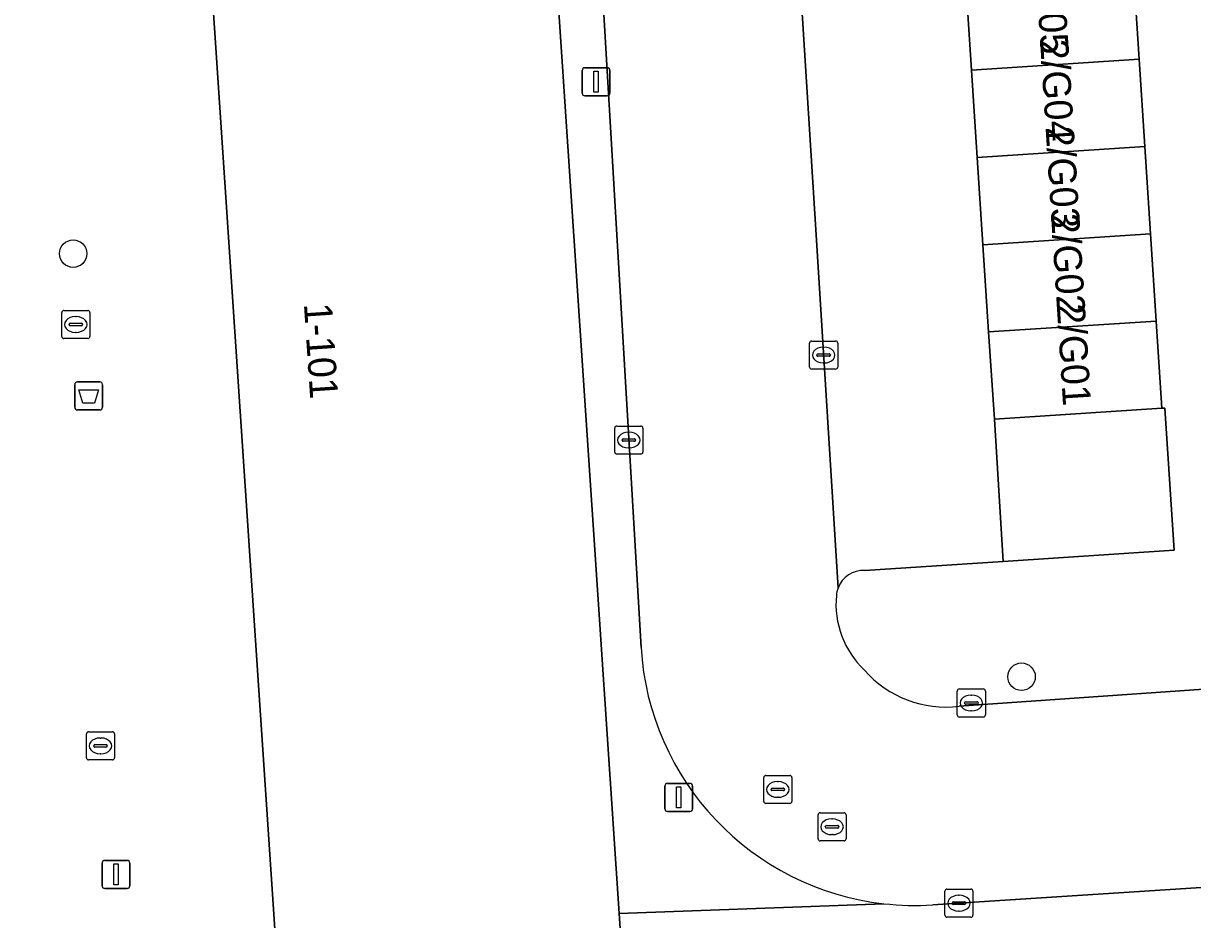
# Model space of a CAD drawing. Extents: x 159680 to 160786, y 387323 to 388340.
# Drawn here: x 160312.93 to 160354.58, y 387760.4 to 387792.33 of the extents above; entities that cross this region are included whole.
import ezdxf

# ---------------------------------------------------------------- set-up
doc = ezdxf.new("R2010")
doc.units = 0
for name, color, linetype in [('IMGEO_Afvalbak', 7, 'Continuous'), ('IMGEO_Boom', 7, 'Continuous'), ('IMGEO_Brandkraan', 7, 'Continuous'), ('IMGEO_Groenvoorziening', 7, 'Continuous'), ('IMGEO_Kolk', 7, 'Continuous'), ('IMGEO_Lichtmast', 7, 'Continuous'), ('IMGEO_Pand', 7, 'Continuous'), ('IMGEO_Pand_nummerreeks', 7, 'Continuous'), ('IMGEO_Parkeervlak_open', 7, 'Continuous'), ('IMGEO_Rijbaan_lokaal_open', 7, 'Continuous'), ('IMGEO_Rioolput', 7, 'Continuous'), ('IMGEO_Voetpad_open', 7, 'Continuous')]:
    doc.layers.add(name, color=color, linetype=linetype)

msp = doc.modelspace()

# ---------------------------------------------------------------- linework, layer by layer
at = {"layer": 'IMGEO_Afvalbak'}
for p, q in [((160314.86, 387779.559), (160315.65, 387779.559)), ((160315.65, 387779.559), (160314.86, 387779.559)), ((160314.76, 387778.659), (160314.76, 387779.459)), ((160314.76, 387779.459), (160314.76, 387778.659)), ((160315.75, 387779.459), (160315.75, 387778.659)), ((160315.75, 387778.659), (160315.75, 387779.459)), ((160315.65, 387778.559), (160314.86, 387778.559)), ((160314.86, 387778.559), (160315.65, 387778.559))]:
    msp.add_line(p, q, dxfattribs=at)
msp.add_lwpolyline([(160314.903, 387779.273), (160315.607, 387779.273), (160315.458, 387778.803), (160315.052, 387778.803), (160314.903, 387779.273)], dxfattribs=at)
for centre, start, end in [((160314.86, 387779.459), 90, 180), ((160314.86, 387779.459), 90, 180), ((160315.65, 387779.459), 0, 90), ((160315.65, 387779.459), 360, 90), ((160314.86, 387778.659), 180, 270), ((160314.86, 387778.659), 180, 270), ((160315.65, 387778.659), 270, 0), ((160315.65, 387778.659), 270, 0)]:
    msp.add_arc(centre, 0.1, start, end, dxfattribs=at)
at = {"layer": 'IMGEO_Boom'}
for centre in [(160314.705, 387784.129), (160348.491, 387769.055)]:
    msp.add_circle(centre, 0.489, dxfattribs=at)
at = {"layer": 'IMGEO_Brandkraan'}
for p, q in [((160341.315, 387764.207), (160342.167, 387764.207)), ((160341.24, 387763.281), (160341.24, 387764.133)), ((160341.542, 387763.75), (160341.94, 387763.75)), ((160341.728, 387763.987), (160341.753, 387763.987)), ((160342.241, 387764.133), (160342.241, 387763.281)), ((160341.499, 387763.701), (160341.499, 387763.713)), ((160341.937, 387763.664), (160341.539, 387763.664)), ((160341.751, 387763.427), (160341.726, 387763.427)), ((160341.983, 387763.713), (160341.983, 387763.701)), ((160342.167, 387763.207), (160341.315, 387763.207))]:
    msp.add_line(p, q, dxfattribs=at)
for points in [[(160341.315, 387764.207), (160342.167, 387764.207)], [(160341.24, 387763.281), (160341.24, 387764.133)], [(160342.241, 387764.133), (160342.241, 387763.281)], [(160342.167, 387763.207), (160341.315, 387763.207)]]:
    msp.add_lwpolyline(points, dxfattribs=at)
for centre, radius, start, end in [((160341.317, 387764.131), 0.0765, 91.552, 178.448), ((160341.317, 387764.131), 0.0765, 91.552, 178.448), ((160342.165, 387764.131), 0.0765, 1.552, 88.448), ((160342.165, 387764.131), 0.0765, 1.552, 88.448), ((160341.539, 387763.71), 0.0403, 85.8775, 175.7526), ((160341.944, 387763.712), 0.0386, 1.7309, 96.639), ((160341.536, 387763.7), 0.0366, 178.938, 274.7102), ((160341.94, 387763.707), 0.043, 264.8664, 352.4533), ((160341.317, 387763.283), 0.0765, 181.552, 268.448), ((160341.317, 387763.283), 0.0765, 181.552, 268.448), ((160342.165, 387763.283), 0.0765, 271.552, 358.448), ((160342.165, 387763.283), 0.0765, 271.552, 358.448)]:
    msp.add_arc(centre, radius, start, end, dxfattribs=at)
for centre, major_axis, ratio, start_param, end_param in [((160341.727, 387763.707), (-0.387, 0.002), 0.722429, 4.712389, 7.853982), ((160341.752, 387763.707), (-0.39, 0.002), 0.717154, 1.570796, 4.712389)]:
    msp.add_ellipse(centre, major_axis=major_axis, ratio=ratio, start_param=start_param, end_param=end_param, dxfattribs=at)
at = {"layer": 'IMGEO_Groenvoorziening'}
msp.add_lwpolyline([(160347.83, 387773.164), (160353.929, 387773.561), (160353.599, 387778.626), (160353.494, 387778.619), (160347.522, 387778.23)], close=True, dxfattribs=at)
at = {"layer": 'IMGEO_Kolk'}
for p, q in [((160314.373, 387782.105), (160315.225, 387782.105)), ((160314.298, 387781.179), (160314.298, 387782.031)), ((160314.6, 387781.648), (160314.998, 387781.648)), ((160314.786, 387781.885), (160314.811, 387781.885)), ((160315.299, 387782.031), (160315.299, 387781.179)), ((160314.557, 387781.599), (160314.557, 387781.611)), ((160314.995, 387781.562), (160314.597, 387781.562)), ((160314.809, 387781.325), (160314.784, 387781.325)), ((160315.041, 387781.611), (160315.041, 387781.599)), ((160315.225, 387781.105), (160314.373, 387781.105)), ((160340.939, 387780.089), (160340.939, 387780.941)), ((160341.014, 387781.015), (160341.866, 387781.015)), ((160341.94, 387780.941), (160341.94, 387780.089)), ((160341.198, 387780.509), (160341.198, 387780.521)), ((160341.636, 387780.472), (160341.238, 387780.472)), ((160341.241, 387780.558), (160341.639, 387780.558)), ((160341.427, 387780.795), (160341.452, 387780.795)), ((160341.682, 387780.521), (160341.682, 387780.509)), ((160341.866, 387780.015), (160341.014, 387780.015)), ((160341.45, 387780.235), (160341.425, 387780.235)), ((160333.998, 387777.061), (160333.998, 387777.913)), ((160334.073, 387777.987), (160334.925, 387777.987)), ((160334.999, 387777.913), (160334.999, 387777.061)), ((160334.257, 387777.481), (160334.257, 387777.493)), ((160334.3, 387777.53), (160334.698, 387777.53)), ((160334.486, 387777.767), (160334.511, 387777.767)), ((160334.741, 387777.493), (160334.741, 387777.481)), ((160334.695, 387777.444), (160334.297, 387777.444)), ((160334.509, 387777.207), (160334.484, 387777.207)), ((160334.925, 387776.987), (160334.073, 387776.987)), ((160346.201, 387767.693), (160346.201, 387768.545)), ((160346.276, 387768.619), (160347.128, 387768.619)), ((160346.689, 387768.399), (160346.714, 387768.399)), ((160347.202, 387768.545), (160347.202, 387767.693)), ((160346.46, 387768.113), (160346.46, 387768.125)), ((160346.898, 387768.076), (160346.5, 387768.076)), ((160346.503, 387768.162), (160346.901, 387768.162)), ((160346.944, 387768.125), (160346.944, 387768.113)), ((160347.128, 387767.619), (160346.276, 387767.619)), ((160346.712, 387767.839), (160346.687, 387767.839)), ((160315.252, 387767.091), (160316.104, 387767.091)), ((160315.177, 387766.165), (160315.177, 387767.017)), ((160315.665, 387766.871), (160315.69, 387766.871)), ((160316.178, 387767.017), (160316.178, 387766.165)), ((160315.436, 387766.585), (160315.436, 387766.597)), ((160315.874, 387766.548), (160315.476, 387766.548)), ((160315.479, 387766.634), (160315.877, 387766.634)), ((160315.688, 387766.311), (160315.663, 387766.311)), ((160315.92, 387766.597), (160315.92, 387766.585)), ((160316.104, 387766.091), (160315.252, 387766.091)), ((160345.759, 387760.56), (160345.759, 387761.412)), ((160345.834, 387761.486), (160346.686, 387761.486)), ((160346.247, 387761.266), (160346.272, 387761.266)), ((160346.76, 387761.412), (160346.76, 387760.56)), ((160346.018, 387760.98), (160346.018, 387760.992)), ((160346.456, 387760.943), (160346.058, 387760.943)), ((160346.061, 387761.029), (160346.459, 387761.029)), ((160346.502, 387760.992), (160346.502, 387760.98)), ((160346.686, 387760.486), (160345.834, 387760.486)), ((160346.27, 387760.706), (160346.245, 387760.706))]:
    msp.add_line(p, q, dxfattribs=at)
for points in [[(160314.373, 387782.105), (160315.225, 387782.105)], [(160314.298, 387781.179), (160314.298, 387782.031)], [(160315.299, 387782.031), (160315.299, 387781.179)], [(160315.225, 387781.105), (160314.373, 387781.105)], [(160340.939, 387780.089), (160340.939, 387780.941)], [(160341.014, 387781.015), (160341.866, 387781.015)], [(160341.94, 387780.941), (160341.94, 387780.089)], [(160341.866, 387780.015), (160341.014, 387780.015)], [(160333.998, 387777.061), (160333.998, 387777.913)], [(160334.073, 387777.987), (160334.925, 387777.987)], [(160334.999, 387777.913), (160334.999, 387777.061)], [(160334.925, 387776.987), (160334.073, 387776.987)], [(160346.201, 387767.693), (160346.201, 387768.545)], [(160346.276, 387768.619), (160347.128, 387768.619)], [(160347.202, 387768.545), (160347.202, 387767.693)], [(160347.128, 387767.619), (160346.276, 387767.619)], [(160315.252, 387767.091), (160316.104, 387767.091)], [(160315.177, 387766.165), (160315.177, 387767.017)], [(160316.178, 387767.017), (160316.178, 387766.165)], [(160316.104, 387766.091), (160315.252, 387766.091)], [(160345.759, 387760.56), (160345.759, 387761.412)], [(160345.834, 387761.486), (160346.686, 387761.486)], [(160346.76, 387761.412), (160346.76, 387760.56)], [(160346.686, 387760.486), (160345.834, 387760.486)]]:
    msp.add_lwpolyline(points, dxfattribs=at)
for centre, radius, start, end in [((160314.375, 387782.029), 0.0765, 91.552, 178.448), ((160314.375, 387782.029), 0.0765, 91.552, 178.448), ((160315.223, 387782.029), 0.0765, 1.552, 88.448), ((160315.223, 387782.029), 0.0765, 1.552, 88.448), ((160314.597, 387781.608), 0.0403, 85.8775, 175.7526), ((160315.002, 387781.61), 0.0386, 1.7309, 96.639), ((160314.594, 387781.598), 0.0366, 178.938, 274.7102), ((160314.998, 387781.605), 0.043, 264.8664, 352.4533), ((160314.375, 387781.181), 0.0765, 181.552, 268.448), ((160314.375, 387781.181), 0.0765, 181.552, 268.448), ((160315.223, 387781.181), 0.0765, 271.552, 358.448), ((160315.223, 387781.181), 0.0765, 271.552, 358.448), ((160341.016, 387780.939), 0.0765, 91.552, 178.448), ((160341.016, 387780.939), 0.0765, 91.552, 178.448), ((160341.864, 387780.939), 0.0765, 1.552, 88.448), ((160341.864, 387780.939), 0.0765, 1.552, 88.448), ((160341.238, 387780.518), 0.0403, 85.8775, 175.7526), ((160341.235, 387780.508), 0.0366, 178.938, 274.7102), ((160341.639, 387780.515), 0.043, 264.8664, 352.4533), ((160341.643, 387780.52), 0.0386, 1.7309, 96.639), ((160341.016, 387780.091), 0.0765, 181.552, 268.448), ((160341.016, 387780.091), 0.0765, 181.552, 268.448), ((160341.864, 387780.091), 0.0765, 271.552, 358.448), ((160341.864, 387780.091), 0.0765, 271.552, 358.448), ((160334.075, 387777.911), 0.0765, 91.552, 178.448), ((160334.075, 387777.911), 0.0765, 91.552, 178.448), ((160334.923, 387777.911), 0.0765, 1.552, 88.448), ((160334.923, 387777.911), 0.0765, 1.552, 88.448), ((160334.297, 387777.49), 0.0403, 85.8775, 175.7526), ((160334.294, 387777.48), 0.0366, 178.938, 274.7102), ((160334.698, 387777.487), 0.043, 264.8664, 352.4533), ((160334.702, 387777.492), 0.0386, 1.7309, 96.639), ((160334.075, 387777.063), 0.0765, 181.552, 268.448), ((160334.075, 387777.063), 0.0765, 181.552, 268.448), ((160334.923, 387777.063), 0.0765, 271.552, 358.448), ((160334.923, 387777.063), 0.0765, 271.552, 358.448), ((160346.278, 387768.543), 0.0765, 91.552, 178.448), ((160346.278, 387768.543), 0.0765, 91.552, 178.448), ((160347.126, 387768.543), 0.0765, 1.552, 88.448), ((160347.126, 387768.543), 0.0765, 1.552, 88.448), ((160346.5, 387768.122), 0.0403, 85.8775, 175.7526), ((160346.497, 387768.112), 0.0366, 178.938, 274.7102), ((160346.901, 387768.119), 0.043, 264.8664, 352.4533), ((160346.905, 387768.124), 0.0386, 1.7309, 96.639), ((160346.278, 387767.695), 0.0765, 181.552, 268.448), ((160346.278, 387767.695), 0.0765, 181.552, 268.448), ((160347.126, 387767.695), 0.0765, 271.552, 358.448), ((160347.126, 387767.695), 0.0765, 271.552, 358.448), ((160315.254, 387767.015), 0.0765, 91.552, 178.448), ((160315.254, 387767.015), 0.0765, 91.552, 178.448), ((160316.102, 387767.015), 0.0765, 1.552, 88.448), ((160316.102, 387767.015), 0.0765, 1.552, 88.448), ((160315.476, 387766.594), 0.0403, 85.8775, 175.7526), ((160315.473, 387766.584), 0.0366, 178.938, 274.7102), ((160315.877, 387766.591), 0.043, 264.8664, 352.4533), ((160315.881, 387766.596), 0.0386, 1.7309, 96.639), ((160315.254, 387766.167), 0.0765, 181.552, 268.448), ((160315.254, 387766.167), 0.0765, 181.552, 268.448), ((160316.102, 387766.167), 0.0765, 271.552, 358.448), ((160316.102, 387766.167), 0.0765, 271.552, 358.448), ((160345.836, 387761.41), 0.0765, 91.552, 178.448), ((160345.836, 387761.41), 0.0765, 91.552, 178.448), ((160346.684, 387761.41), 0.0765, 1.552, 88.448), ((160346.684, 387761.41), 0.0765, 1.552, 88.448), ((160346.058, 387760.989), 0.0403, 85.8775, 175.7526), ((160346.055, 387760.979), 0.0366, 178.938, 274.7102), ((160346.459, 387760.986), 0.043, 264.8664, 352.4533), ((160346.463, 387760.991), 0.0386, 1.7309, 96.639), ((160345.836, 387760.562), 0.0765, 181.552, 268.448), ((160345.836, 387760.562), 0.0765, 181.552, 268.448), ((160346.684, 387760.562), 0.0765, 271.552, 358.448), ((160346.684, 387760.562), 0.0765, 271.552, 358.448)]:
    msp.add_arc(centre, radius, start, end, dxfattribs=at)
for centre, major_axis, ratio, start_param, end_param in [((160314.785, 387781.605), (-0.387, 0.002), 0.722429, 4.712389, 7.853982), ((160314.81, 387781.605), (-0.39, 0.002), 0.717154, 1.570796, 4.712389), ((160341.426, 387780.515), (-0.387, 0.002), 0.722429, 4.712389, 7.853982), ((160341.451, 387780.515), (-0.39, 0.002), 0.717154, 1.570796, 4.712389), ((160334.485, 387777.487), (-0.387, 0.002), 0.722429, 4.712389, 7.853982), ((160334.51, 387777.487), (-0.39, 0.002), 0.717154, 1.570796, 4.712389), ((160346.688, 387768.119), (-0.387, 0.002), 0.722429, 4.712389, 7.853982), ((160346.713, 387768.119), (-0.39, 0.002), 0.717154, 1.570796, 4.712389), ((160315.664, 387766.591), (-0.387, 0.002), 0.722429, 4.712389, 7.853982), ((160315.689, 387766.591), (-0.39, 0.002), 0.717154, 1.570796, 4.712389), ((160346.246, 387760.986), (-0.387, 0.002), 0.722429, 4.712389, 7.853982), ((160346.271, 387760.986), (-0.39, 0.002), 0.717154, 1.570796, 4.712389)]:
    msp.add_ellipse(centre, major_axis=major_axis, ratio=ratio, start_param=start_param, end_param=end_param, dxfattribs=at)
at = {"layer": 'IMGEO_Lichtmast'}
for p, q in [((160332.837, 387789.852), (160332.837, 387790.652)), ((160332.837, 387790.652), (160332.837, 387789.852)), ((160332.937, 387790.752), (160333.727, 387790.752)), ((160333.727, 387790.752), (160332.937, 387790.752)), ((160333.827, 387790.652), (160333.827, 387789.852)), ((160333.827, 387789.852), (160333.827, 387790.652)), ((160333.727, 387789.752), (160332.937, 387789.752)), ((160332.937, 387789.752), (160333.727, 387789.752)), ((160335.782, 387764.352), (160335.782, 387765.152)), ((160335.782, 387765.152), (160335.782, 387764.352)), ((160335.882, 387765.252), (160336.672, 387765.252)), ((160336.672, 387765.252), (160335.882, 387765.252)), ((160336.772, 387765.152), (160336.772, 387764.352)), ((160336.772, 387764.352), (160336.772, 387765.152)), ((160336.672, 387764.252), (160335.882, 387764.252)), ((160335.882, 387764.252), (160336.672, 387764.252)), ((160315.833, 387762.509), (160316.623, 387762.509)), ((160316.623, 387762.509), (160315.833, 387762.509)), ((160315.733, 387761.609), (160315.733, 387762.409)), ((160315.733, 387762.409), (160315.733, 387761.609)), ((160316.723, 387762.409), (160316.723, 387761.609)), ((160316.723, 387761.609), (160316.723, 387762.409)), ((160316.623, 387761.509), (160315.833, 387761.509)), ((160315.833, 387761.509), (160316.623, 387761.509))]:
    msp.add_line(p, q, dxfattribs=at)
for points in [[(160333.257, 387790.627), (160333.407, 387790.627), (160333.407, 387789.877), (160333.257, 387789.877), (160333.257, 387790.627)], [(160336.202, 387765.127), (160336.352, 387765.127), (160336.352, 387764.377), (160336.202, 387764.377), (160336.202, 387765.127)], [(160316.153, 387762.384), (160316.303, 387762.384), (160316.303, 387761.634), (160316.153, 387761.634), (160316.153, 387762.384)]]:
    msp.add_lwpolyline(points, dxfattribs=at)
for centre, start, end in [((160332.937, 387790.652), 90, 180), ((160332.937, 387790.652), 90, 180), ((160333.727, 387790.652), 0, 90), ((160333.727, 387790.652), 360, 90), ((160332.937, 387789.852), 180, 270), ((160332.937, 387789.852), 180, 270), ((160333.727, 387789.852), 270, 0), ((160333.727, 387789.852), 270, 0), ((160335.882, 387765.152), 90, 180), ((160335.882, 387765.152), 90, 180), ((160336.672, 387765.152), 0, 90), ((160336.672, 387765.152), 360, 90), ((160335.882, 387764.352), 180, 270), ((160335.882, 387764.352), 180, 270), ((160336.672, 387764.352), 270, 0), ((160336.672, 387764.352), 270, 0), ((160315.833, 387762.409), 90, 180), ((160315.833, 387762.409), 90, 180), ((160316.623, 387762.409), 0, 90), ((160316.623, 387762.409), 360, 90), ((160315.833, 387761.609), 180, 270), ((160315.833, 387761.609), 180, 270), ((160316.623, 387761.609), 270, 0), ((160316.623, 387761.609), 270, 0)]:
    msp.add_arc(centre, 0.1, start, end, dxfattribs=at)
at = {"layer": 'IMGEO_Pand'}
for points in [[(160331.352, 387802.523), (160319.097, 387801.761), (160322.017, 387758.116), (160322.036, 387757.833), (160333.839, 387758.606), (160334.288, 387758.635), (160334.155, 387760.62)], [(160346.711, 387790.665), (160352.683, 387791.054), (160352.481, 387794.163), (160346.509, 387793.774)], [(160346.914, 387787.556), (160352.886, 387787.945), (160352.683, 387791.054), (160346.711, 387790.665)], [(160347.117, 387784.447), (160353.089, 387784.837), (160352.886, 387787.945), (160346.914, 387787.556)], [(160347.319, 387781.338), (160353.291, 387781.728), (160353.089, 387784.837), (160347.117, 387784.447)], [(160353.494, 387778.619), (160353.291, 387781.728), (160347.319, 387781.338), (160347.522, 387778.23)]]:
    msp.add_lwpolyline(points, close=True, dxfattribs=at)
at = {"layer": 'IMGEO_Parkeervlak_open'}
for points in [[(160338.406, 387828.202), (160339.882, 387805.311), (160341.198, 387784.423), (160341.952, 387772.208)], [(160342.911, 387772.843), (160347.83, 387773.164), (160347.522, 387778.23), (160347.319, 387781.338), (160347.117, 387784.447), (160346.914, 387787.556), (160346.711, 387790.665), (160346.509, 387793.774), (160346.306, 387796.883), (160346.103, 387799.991), (160345.9, 387803.1)]]:
    msp.add_lwpolyline(points, dxfattribs=at)
msp.add_arc((160342.868, 387771.866), 0.978, 87.4737, 159.5472, dxfattribs=at)
at = {"layer": 'IMGEO_Rijbaan_lokaal_open'}
for points in [[(160341.952, 387772.208), (160341.198, 387784.423), (160339.882, 387805.311), (160338.406, 387828.202), (160338.395, 387828.368)], [(160331.665, 387822.773), (160332.752, 387806.497), (160332.954, 387803.761), (160334.935, 387770.099)], [(160345.325, 387760.926), (160375.86, 387762.898), (160379.928, 387763.183), (160386.304, 387763.634), (160385.716, 387771.751)], [(160358.917, 387768.881), (160346.266, 387768.001)]]:
    msp.add_lwpolyline(points, dxfattribs=at)
for centre, radius, start, end in [((160342.816, 387771.877), 0.925, 159.0409, 175.2336), ((160345.142, 387771.649), 3.263, 174.641, 226.4146), ((160344.685, 387770.671), 9.766, 183.3604, 263.5474), ((160345.806, 387771.862), 3.889, 221.4928, 276.7969), ((160344.687, 387770.734), 9.829, 263.5748, 273.7224)]:
    msp.add_arc(centre, radius, start, end, dxfattribs=at)
at = {"layer": 'IMGEO_Rioolput'}
for p, q in [((160339.306, 387764.612), (160339.306, 387765.464)), ((160339.381, 387765.538), (160340.233, 387765.538)), ((160340.307, 387765.464), (160340.307, 387764.612)), ((160339.565, 387765.032), (160339.565, 387765.044)), ((160340.003, 387764.995), (160339.605, 387764.995)), ((160339.608, 387765.081), (160340.006, 387765.081)), ((160339.794, 387765.318), (160339.819, 387765.318)), ((160340.049, 387765.044), (160340.049, 387765.032)), ((160339.817, 387764.758), (160339.792, 387764.758)), ((160340.233, 387764.538), (160339.381, 387764.538))]:
    msp.add_line(p, q, dxfattribs=at)
for points in [[(160339.306, 387764.612), (160339.306, 387765.464)], [(160339.381, 387765.538), (160340.233, 387765.538)], [(160340.307, 387765.464), (160340.307, 387764.612)], [(160340.233, 387764.538), (160339.381, 387764.538)]]:
    msp.add_lwpolyline(points, dxfattribs=at)
for centre, radius, start, end in [((160339.383, 387765.462), 0.0765, 91.552, 178.448), ((160339.383, 387765.462), 0.0765, 91.552, 178.448), ((160340.231, 387765.462), 0.0765, 1.552, 88.448), ((160340.231, 387765.462), 0.0765, 1.552, 88.448), ((160339.605, 387765.041), 0.0403, 85.8775, 175.7526), ((160339.602, 387765.031), 0.0366, 178.938, 274.7102), ((160340.006, 387765.038), 0.043, 264.8664, 352.4533), ((160340.01, 387765.043), 0.0386, 1.7309, 96.639), ((160339.383, 387764.614), 0.0765, 181.552, 268.448), ((160339.383, 387764.614), 0.0765, 181.552, 268.448), ((160340.231, 387764.614), 0.0765, 271.552, 358.448), ((160340.231, 387764.614), 0.0765, 271.552, 358.448)]:
    msp.add_arc(centre, radius, start, end, dxfattribs=at)
for centre, major_axis, ratio, start_param, end_param in [((160339.793, 387765.038), (-0.387, 0.002), 0.722429, 4.712389, 7.853982), ((160339.818, 387765.038), (-0.39, 0.002), 0.717154, 1.570796, 4.712389)]:
    msp.add_ellipse(centre, major_axis=major_axis, ratio=ratio, start_param=start_param, end_param=end_param, dxfattribs=at)
at = {"layer": 'IMGEO_Voetpad_open'}
for points in [[(160339.407, 387827.52), (160344.279, 387827.97), (160350.251, 387828.36), (160350.454, 387825.251), (160350.656, 387822.142), (160350.859, 387819.034), (160351.062, 387815.925), (160351.264, 387812.816), (160351.467, 387809.707), (160351.67, 387806.598), (160351.872, 387803.49), (160352.075, 387800.381), (160352.278, 387797.272), (160352.481, 387794.163), (160352.683, 387791.054), (160352.886, 387787.945), (160353.089, 387784.837), (160353.291, 387781.728), (160353.494, 387778.619), (160353.599, 387778.626), (160353.929, 387773.561), (160347.83, 387773.164), (160342.911, 387772.843)], [(160331.86, 387807.147), (160328.12, 387806.893), (160327.133, 387821.44), (160325.609, 387821.289), (160326.659, 387805.594), (160327.861, 387805.674), (160327.902, 387805.056), (160327.719, 387805.043), (160327.791, 387803.958), (160331.695, 387804.219), (160331.738, 387803.578), (160331.283, 387803.548), (160331.352, 387802.523), (160334.155, 387760.62), (160343.587, 387760.967)], [(160334.935, 387770.099), (160332.954, 387803.761)], [(160267.045, 387757.179), (160305.293, 387759.637), (160305.552, 387755.65), (160314.074, 387756.196), (160314.413, 387750.902), (160314.471, 387750), (160314.558, 387748.644), (160316.917, 387748.799), (160321.422, 387749.095), (160321.394, 387749.39), (160322.546, 387749.466), (160322.428, 387751.404), (160322.036, 387757.833), (160322.017, 387758.116), (160319.097, 387801.761)], [(160346.266, 387768.001), (160358.917, 387768.881)], [(160379.961, 387762.685), (160379.928, 387763.183), (160375.86, 387762.898), (160345.325, 387760.926)], [(160343.587, 387760.967), (160334.155, 387760.62), (160334.288, 387758.635), (160334.3, 387758.424), (160334.654, 387752.114), (160334.757, 387750.277), (160334.77, 387750.067), (160340.756, 387750.466), (160340.787, 387750), (160341.127, 387744.922), (160334.957, 387744.51), (160338.038, 387698.462), (160345.545, 387699.18)]]:
    msp.add_lwpolyline(points, dxfattribs=at)
for centre, radius, start, end in [((160342.868, 387771.866), 0.978, 87.4737, 159.5472), ((160342.816, 387771.877), 0.925, 159.0409, 175.2336), ((160345.142, 387771.649), 3.263, 174.641, 226.4146), ((160344.685, 387770.671), 9.766, 183.3604, 263.5474), ((160345.806, 387771.862), 3.889, 221.4928, 276.7969), ((160344.687, 387770.734), 9.829, 263.5748, 273.7224)]:
    msp.add_arc(centre, radius, start, end, dxfattribs=at)

# ---------------------------------------------------------------- texts
at = {"layer": 'IMGEO_Pand_nummerreeks'}
for s, rotation, p in [('2/G05', 273.6085, (160348.953, 387794.845)), ('2/G04', 273.6085, (160349.149, 387791.74)), ('2/G03', 273.6085, (160349.345, 387788.636)), ('2/G02', 273.6085, (160349.54, 387785.537)), ('1-101', 273.8271, (160322.922, 387782.341)), ('2/G01', 273.6085, (160349.743, 387782.316))]:
    msp.add_text(s, height=1, rotation=rotation, dxfattribs=at).set_placement(p)

doc.saveas('drawing.dxf')
